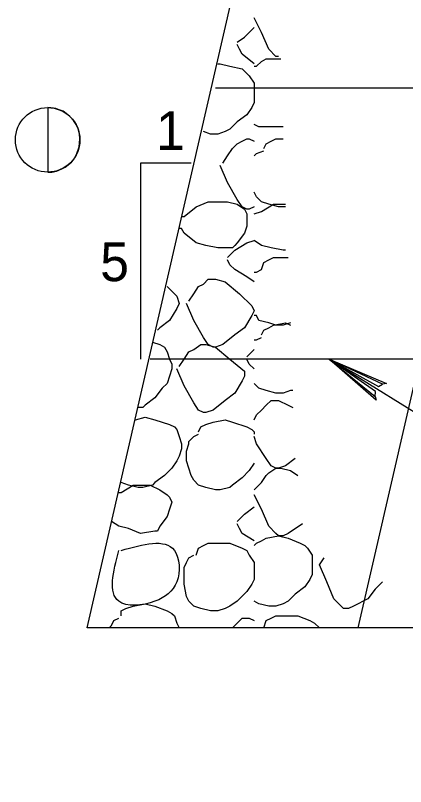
# Model space of a CAD drawing. Extents: x 593 to 1473, y 721 to 1315.
# Drawn here: x 987.5 to 1017.8, y 818.6 to 878.4 of the extents above; entities that cross this region are included whole.
import ezdxf

# ---------------------------------------------------------------- set-up
doc = ezdxf.new("R2010")
doc.units = 0
doc.layers.add('1', color=7, linetype='Continuous')
doc.layers.add('2', color=7, linetype='Continuous')

msp = doc.modelspace()

# ---------------------------------------------------------------- linework, layer by layer
at = {"layer": '1'}
msp.add_lwpolyline([(990.028, 871.224), (990.028, 866.22), (990.347, 866.231), (990.72, 866.305), (991.125, 866.465), (991.381, 866.604), (991.626, 866.785), (991.861, 866.999), (992.042, 867.212), (992.298, 867.66), (992.479, 868.194), (992.532, 868.781), (992.49, 869.197), (992.394, 869.581), (992.234, 869.922), (992.031, 870.232), (991.744, 870.541), (991.467, 870.765), (991.221, 870.936), (990.923, 871.043), (990.656, 871.15), (990.486, 871.182), (990.283, 871.214)], close=True, dxfattribs=at)
msp.add_lwpolyline([(1015.402, 848.857), (1015.432, 849.226), (1011.844, 851.735), (1015.402, 848.857), (1015.495, 848.565), (1011.844, 851.735), (1015.67, 849.616), (1015.977, 849.808), (1011.844, 851.735), (1016.3, 849.864), (1015.977, 849.808)], dxfattribs=at)
msp.add_lwpolyline([(1015.402, 848.857), (1015.432, 849.226), (1011.844, 851.735), (1015.402, 848.857), (1015.495, 848.565), (1011.844, 851.735), (1015.67, 849.616), (1015.977, 849.808), (1011.844, 851.735), (1016.3, 849.864), (1015.977, 849.808)], dxfattribs=at)
msp.add_circle((990.028, 868.722), 2.502, dxfattribs=at)
at = {"layer": '2'}
for p, q in [((993.094, 830.922), (1006.031, 887.172)), ((1014.094, 830.922), (1027.031, 887.172)), ((1037.531, 872.735), (1003.031, 872.735)), ((990.028, 871.224), (990.028, 866.22)), ((1001.156, 866.922), (997.219, 866.922)), ((997.219, 866.922), (997.219, 851.735)), ((1047.844, 851.735), (997.969, 851.735)), ((1011.844, 851.735), (1065.226, 818.633)), ((1027.969, 830.922), (993.094, 830.922))]:
    msp.add_line(p, q, dxfattribs=at)
for points in [[(1006.594, 877.047), (1006.031, 878.172)], [(1005.281, 876.672), (1006.031, 877.422)], [(1007.156, 875.735), (1006.594, 877.047)], [(1004.719, 876.297), (1005.281, 876.672)], [(1004.906, 875.735), (1004.719, 876.11)], [(1005.094, 875.36), (1004.906, 875.735)], [(1007.719, 875.172), (1007.156, 875.735)], [(1006.031, 874.61), (1005.094, 875.36)], [(1007.906, 875.172), (1007.719, 875.172)], [(1007.906, 875.172), (1007.906, 875.172)], [(1003.219, 874.61), (1003.406, 874.61)], [(1003.406, 874.61), (1004.156, 874.422)], [(1004.156, 874.422), (1005.094, 874.235)], [(1006.031, 874.422), (1006.219, 874.422)], [(1006.219, 874.422), (1006.594, 874.797)], [(1006.594, 874.797), (1006.969, 874.985)], [(1006.969, 874.985), (1007.906, 874.985)], [(1007.906, 874.985), (1008.094, 874.985)], [(1005.094, 874.235), (1005.469, 873.86)], [(1005.469, 873.86), (1005.656, 873.672)], [(1005.656, 873.672), (1006.031, 873.11)], [(1006.031, 873.11), (1006.031, 872.547)], [(1006.031, 872.547), (1006.031, 872.172)], [(1006.031, 872.172), (1006.031, 871.61)], [(1006.031, 871.61), (1005.844, 871.235)], [(1005.844, 871.235), (1005.469, 870.672)], [(1005.469, 870.672), (1004.719, 870.11)], [(1004.719, 870.11), (1004.156, 869.547)], [(1006.406, 869.735), (1006.031, 869.922)], [(1007.156, 869.735), (1006.406, 869.735)], [(1007.719, 869.735), (1007.156, 869.735)], [(1008.281, 869.735), (1007.719, 869.735)], [(1002.656, 869.172), (1002.094, 869.36)], [(1003.219, 869.172), (1002.656, 869.172)], [(1003.781, 869.36), (1003.219, 869.172)], [(1004.156, 869.547), (1003.781, 869.36)], [(1004.719, 868.422), (1005.094, 868.61)], [(1005.094, 868.61), (1005.469, 868.797)], [(1005.469, 868.797), (1005.656, 868.797)], [(1005.656, 868.797), (1006.031, 868.61)], [(1006.969, 868.422), (1007.344, 868.61)], [(1007.344, 868.61), (1007.719, 868.797)], [(1007.719, 868.797), (1008.281, 868.797)], [(1003.969, 867.485), (1004.344, 868.047)], [(1004.344, 868.047), (1004.719, 868.422)], [(1006.219, 867.672), (1006.781, 867.86)], [(1006.781, 868.047), (1006.969, 868.422)], [(1003.594, 866.922), (1003.969, 867.485)], [(1006.031, 867.485), (1006.219, 867.672)], [(1003.969, 865.422), (1003.406, 866.735)], [(1004.719, 864.11), (1003.969, 865.422)], [(1006.219, 864.297), (1006.031, 864.672)], [(1006.594, 863.922), (1006.219, 864.297)], [(1001.531, 863.547), (1002.469, 863.922)], [(1002.469, 863.922), (1002.844, 863.922)], [(1002.844, 863.922), (1003.406, 863.922)], [(1003.406, 863.922), (1003.969, 863.922)], [(1003.969, 863.922), (1004.719, 863.735)], [(1005.094, 863.547), (1004.719, 864.11)], [(1004.719, 863.735), (1005.281, 863.36)], [(1007.156, 863.735), (1006.594, 863.922)], [(1006.594, 863.172), (1007.531, 863.735)], [(1007.906, 863.547), (1007.156, 863.735)], [(1007.531, 863.735), (1007.906, 863.735)], [(1007.906, 863.735), (1008.469, 863.735)], [(1000.594, 862.797), (1001.531, 863.547)], [(1005.469, 863.36), (1005.094, 863.547)], [(1005.281, 863.36), (1005.469, 862.985)], [(1005.656, 863.36), (1005.469, 863.36)], [(1006.031, 863.547), (1005.656, 863.36)], [(1006.031, 862.985), (1006.594, 863.172)], [(1008.469, 863.547), (1007.906, 863.547)], [(1000.406, 862.797), (1000.594, 862.797)], [(1005.469, 862.985), (1005.469, 862.797)], [(1005.469, 862.797), (1005.469, 862.047)], [(1000.406, 861.86), (1000.219, 861.86)], [(1000.594, 861.485), (1000.406, 861.86)], [(1005.469, 862.047), (1005.281, 861.485)], [(1001.531, 860.735), (1000.594, 861.485)], [(1005.281, 861.485), (1004.719, 860.735)], [(1002.281, 860.547), (1001.531, 860.735)], [(1004.531, 860.172), (1005.469, 860.735)], [(1004.719, 860.735), (1004.531, 860.547)], [(1005.469, 860.735), (1006.031, 860.922)], [(1006.594, 860.547), (1006.031, 860.922)], [(1003.219, 860.36), (1002.281, 860.547)], [(1004.344, 860.36), (1003.219, 860.36)], [(1003.969, 859.61), (1004.531, 860.172)], [(1004.531, 860.547), (1004.344, 860.36)], [(1007.344, 860.36), (1006.594, 860.547)], [(1008.281, 860.172), (1007.344, 860.36)], [(1008.469, 860.172), (1008.281, 860.172)], [(1007.156, 859.422), (1007.531, 859.61)], [(1007.531, 859.61), (1008.469, 859.61)], [(1008.469, 859.61), (1008.656, 859.61)], [(1004.156, 859.047), (1003.969, 859.422)], [(1004.531, 858.672), (1004.156, 859.047)], [(1006.594, 858.672), (1006.781, 859.235)], [(1006.781, 859.235), (1007.156, 859.422)], [(1005.469, 858.11), (1004.531, 858.672)], [(1006.031, 858.485), (1006.219, 858.485)], [(1006.219, 858.485), (1006.594, 858.672)], [(1002.094, 857.547), (1002.469, 857.922)], [(1002.469, 857.922), (1002.844, 857.922)], [(1002.844, 857.922), (1003.031, 857.922)], [(1003.031, 857.922), (1003.781, 857.735)], [(1003.781, 857.735), (1004.906, 856.797)], [(1006.031, 857.735), (1005.469, 858.11)], [(999.281, 857.36), (1000.031, 856.61)], [(1001.344, 856.797), (1001.719, 857.36)], [(1001.719, 857.36), (1002.094, 857.547)], [(1000.031, 856.61), (1000.219, 856.047)], [(1000.969, 856.235), (1001.344, 856.797)], [(1004.906, 856.797), (1005.844, 855.86)], [(1000.219, 856.047), (1000.031, 855.672)], [(1001.344, 854.735), (1000.781, 856.047)], [(1000.031, 855.672), (999.469, 854.735)], [(1005.844, 855.86), (1006.031, 855.485)], [(1006.031, 855.485), (1005.844, 855.11)], [(999.469, 854.735), (998.719, 854.172)], [(1002.094, 853.422), (1001.344, 854.735)], [(1005.844, 855.11), (1005.281, 854.172)], [(1006.219, 855.11), (1006.031, 855.11)], [(1006.406, 854.735), (1006.219, 855.11)], [(1007.156, 854.547), (1006.406, 854.735)], [(998.719, 854.172), (998.531, 853.985)], [(1005.281, 854.172), (1004.531, 853.61)], [(1006.781, 853.985), (1007.156, 854.172)], [(1007.719, 854.36), (1007.156, 854.547)], [(1007.156, 854.172), (1007.531, 854.36)], [(1007.531, 854.36), (1008.469, 854.547)], [(1008.281, 854.36), (1007.719, 854.36)], [(1008.844, 854.547), (1008.281, 854.36)], [(1008.469, 854.547), (1008.844, 854.36)], [(1004.531, 853.61), (1003.594, 852.86)], [(1006.594, 853.61), (1006.781, 853.985)], [(998.156, 853.047), (998.719, 852.86)], [(1002.469, 852.86), (1002.094, 853.422)], [(1006.031, 853.235), (1006.219, 853.235)], [(1006.219, 853.235), (1006.594, 853.422)], [(998.719, 852.86), (999.094, 852.672)], [(999.094, 852.672), (999.281, 852.297)], [(1000.969, 852.297), (1001.344, 852.485)], [(1001.344, 852.485), (1001.906, 852.86)], [(1001.906, 852.86), (1002.094, 852.86)], [(1002.094, 852.86), (1002.281, 852.86)], [(1002.281, 852.86), (1003.031, 852.672)], [(1002.844, 852.672), (1002.469, 852.86)], [(1003.031, 852.672), (1002.844, 852.672)], [(1003.594, 852.86), (1003.031, 852.672)], [(1003.031, 852.672), (1004.156, 851.735)], [(1005.469, 851.922), (1006.031, 852.485)], [(1006.031, 852.485), (1006.031, 852.485)], [(999.281, 852.297), (999.469, 851.735)], [(999.469, 851.735), (999.656, 851.36)], [(1000.219, 851.172), (1000.594, 851.735)], [(1000.594, 851.735), (1000.969, 852.297)], [(1004.156, 851.735), (1005.281, 850.797)], [(1005.656, 851.36), (1005.469, 851.735)], [(999.656, 851.36), (999.656, 850.985)], [(1006.031, 850.985), (1005.656, 851.36)], [(999.656, 850.985), (999.469, 850.422)], [(1000.594, 849.672), (1000.031, 850.985)], [(1005.281, 850.797), (1005.281, 850.422)], [(1006.031, 850.985), (1006.031, 850.985)], [(999.469, 850.422), (999.281, 849.86)], [(1005.094, 850.047), (1004.531, 849.11)], [(1005.281, 850.422), (1005.094, 850.047)], [(998.906, 849.485), (998.344, 848.735)], [(999.281, 849.86), (998.906, 849.485)], [(1001.344, 848.36), (1000.594, 849.672)], [(1006.406, 849.485), (1006.031, 849.86)], [(1006.031, 849.86), (1006.031, 849.86)], [(1006.969, 849.297), (1006.406, 849.485)], [(998.344, 848.735), (997.594, 848.172)], [(1004.531, 849.11), (1003.781, 848.547)], [(1007.719, 849.11), (1006.969, 849.297)], [(1008.281, 849.11), (1007.719, 849.11)], [(1008.844, 849.297), (1008.281, 849.11)], [(1009.031, 849.297), (1008.844, 849.297)], [(997.594, 848.172), (997.406, 847.985)], [(1001.719, 847.797), (1001.344, 848.36)], [(1003.781, 848.547), (1002.844, 847.797)], [(1006.594, 847.797), (1006.969, 848.172)], [(1006.969, 848.172), (1007.344, 848.547)], [(1007.344, 848.547), (1007.719, 848.547)], [(1007.719, 848.547), (1007.906, 848.547)], [(1007.906, 848.547), (1008.656, 848.172)], [(1008.656, 848.172), (1009.031, 847.985)], [(997.406, 847.985), (997.031, 847.985)], [(1002.094, 847.61), (1001.719, 847.797)], [(1002.281, 847.61), (1002.094, 847.61)], [(1002.844, 847.797), (1002.281, 847.61)], [(1006.219, 847.422), (1006.594, 847.797)], [(996.844, 847.047), (997.594, 847.235)], [(997.594, 847.235), (998.344, 847.047)], [(998.344, 847.047), (999.469, 846.672)], [(1002.844, 846.86), (1003.781, 847.047)], [(1003.781, 847.047), (1004.344, 846.86)], [(1006.031, 847.047), (1006.219, 847.422)], [(999.469, 846.672), (999.844, 846.485)], [(999.844, 846.485), (1000.031, 846.297)], [(1001.719, 846.11), (1001.906, 846.485)], [(1001.906, 846.485), (1002.281, 846.672)], [(1002.281, 846.672), (1002.844, 846.86)], [(1004.344, 846.86), (1005.469, 846.485)], [(1005.469, 846.485), (1005.844, 846.297)], [(1000.031, 846.297), (1000.219, 845.735)], [(1000.219, 845.735), (1000.406, 845.172)], [(1000.969, 845.36), (1001.344, 845.735)], [(1001.344, 845.735), (1001.719, 845.922)], [(1005.844, 846.297), (1006.031, 846.11)], [(1006.031, 846.11), (1006.031, 845.922)], [(1006.219, 845.172), (1006.031, 845.735)], [(1000.406, 845.172), (1000.406, 844.797)], [(1000.781, 844.61), (1000.969, 845.172)], [(1000.969, 845.172), (1000.969, 845.36)], [(1006.969, 844.047), (1006.219, 845.172)], [(1000.406, 844.797), (1000.219, 844.235)], [(1000.781, 843.86), (1000.781, 844.61)], [(1000.219, 844.235), (1000.031, 843.86)], [(1007.344, 843.485), (1006.969, 844.047)], [(1009.219, 844.047), (1008.469, 843.485)], [(1000.031, 843.86), (999.656, 843.297)], [(1001.156, 842.735), (1000.781, 843.86)], [(1006.031, 843.672), (1005.656, 843.11)], [(1006.031, 843.672), (1006.031, 843.672)], [(1007.719, 843.297), (1007.344, 843.485)], [(1008.469, 843.485), (1007.906, 843.297)], [(999.656, 843.297), (999.094, 842.735)], [(1005.656, 843.11), (1005.094, 842.547)], [(1006.969, 842.735), (1007.156, 842.922)], [(1007.156, 842.922), (1007.719, 843.297)], [(1007.719, 843.297), (1007.906, 843.297)], [(1007.906, 843.297), (1007.719, 843.297)], [(1007.906, 843.297), (1008.094, 843.297)], [(1008.094, 843.297), (1008.844, 843.11)], [(1008.844, 843.11), (1009.406, 842.735)], [(996.281, 841.985), (995.719, 842.172)], [(998.344, 842.172), (998.156, 841.985)], [(999.094, 842.735), (998.344, 842.172)], [(1001.344, 842.36), (1001.156, 842.735)], [(1001.719, 841.985), (1001.344, 842.36)], [(1005.094, 842.547), (1004.344, 841.985)], [(1006.031, 841.61), (1006.594, 842.172)], [(1006.594, 842.172), (1006.969, 842.735)], [(995.719, 841.422), (996.656, 841.985)], [(997.031, 841.797), (996.281, 841.985)], [(996.656, 841.985), (996.844, 841.985)], [(996.844, 841.985), (997.594, 841.985)], [(997.406, 841.797), (997.031, 841.797)], [(998.156, 841.985), (997.406, 841.797)], [(997.594, 841.985), (997.969, 841.985)], [(997.969, 841.985), (998.719, 841.61)], [(998.719, 841.61), (999.281, 841.235)], [(1002.281, 841.797), (1001.719, 841.985)], [(1003.031, 841.61), (1002.281, 841.797)], [(1003.406, 841.61), (1003.031, 841.61)], [(1004.156, 841.797), (1003.406, 841.61)], [(1004.344, 841.985), (1004.156, 841.797)], [(995.531, 841.422), (995.719, 841.422)], [(999.281, 841.235), (999.469, 841.047)], [(999.469, 841.047), (999.656, 840.672)], [(1006.594, 840.11), (1006.031, 841.235)], [(999.656, 840.672), (999.469, 840.11)], [(999.469, 840.11), (999.281, 839.547)], [(1005.281, 839.735), (1006.031, 840.297)], [(1007.156, 838.797), (1006.594, 840.11)], [(995.531, 838.797), (994.969, 839.172)], [(999.281, 839.547), (998.719, 838.797)], [(1004.719, 839.172), (1005.281, 839.735)], [(996.281, 838.61), (995.531, 838.797)], [(997.219, 838.235), (996.281, 838.61)], [(998.719, 838.797), (998.531, 838.422)], [(1004.906, 838.61), (1004.719, 838.985)], [(1005.094, 838.235), (1004.906, 838.61)], [(1007.719, 838.235), (1007.156, 838.797)], [(1009.781, 838.985), (1008.656, 838.235)], [(1009.781, 838.985), (1009.781, 838.985)], [(998.344, 838.422), (997.219, 838.235)], [(998.531, 838.422), (998.344, 838.422)], [(1006.031, 837.672), (1005.094, 838.235)], [(1006.969, 837.86), (1007.906, 838.047)], [(1007.906, 838.047), (1007.719, 838.235)], [(1007.906, 838.047), (1008.656, 837.86)], [(1008.281, 838.047), (1007.906, 838.047)], [(1008.656, 838.235), (1008.281, 838.047)], [(1002.094, 837.297), (1002.469, 837.485)], [(1002.469, 837.485), (1003.406, 837.485)], [(1003.406, 837.485), (1004.156, 837.485)], [(1004.156, 837.485), (1005.094, 837.11)], [(1006.031, 837.297), (1006.219, 837.485)], [(1006.219, 837.485), (1006.594, 837.672)], [(1006.594, 837.672), (1006.969, 837.86)], [(1008.656, 837.86), (1009.594, 837.485)], [(1009.594, 837.485), (1009.969, 837.297)], [(1001.531, 836.547), (1001.719, 837.11)], [(1001.719, 837.11), (1002.094, 837.297)], [(1005.094, 837.11), (1005.469, 836.922)], [(1005.469, 836.922), (1005.656, 836.547)], [(1009.969, 837.297), (1010.156, 837.11)], [(1010.156, 837.11), (1010.531, 836.547)], [(1000.781, 835.985), (1000.969, 836.36)], [(1000.969, 836.36), (1001.344, 836.547)], [(1005.656, 836.547), (1006.031, 835.985)], [(1010.531, 836.547), (1010.531, 835.985)], [(1011.094, 835.797), (1011.469, 836.36)], [(1000.594, 835.61), (1000.781, 835.985)], [(1000.594, 835.047), (1000.594, 835.61)], [(1006.031, 835.985), (1006.031, 835.61)], [(1006.031, 835.61), (1006.031, 835.235)], [(1010.531, 835.985), (1010.531, 835.61)], [(1010.531, 835.61), (1010.531, 835.047)], [(1011.656, 834.485), (1011.094, 835.797)], [(1000.594, 834.297), (1000.594, 835.047)], [(1006.031, 835.235), (1006.031, 834.672)], [(1010.531, 835.047), (1010.344, 834.672)], [(1006.031, 834.672), (1005.844, 834.297)], [(1010.344, 834.672), (1009.969, 834.11)], [(1012.219, 833.172), (1011.656, 834.485)], [(1015.969, 834.485), (1015.406, 833.922)], [(1000.781, 833.36), (1000.594, 834.297)], [(1005.844, 834.297), (1005.469, 833.735)], [(1009.969, 834.11), (1009.219, 833.547)], [(1015.406, 833.922), (1014.844, 833.172)], [(1000.969, 832.985), (1000.781, 833.36)], [(1005.469, 833.735), (1004.719, 832.985)], [(1009.219, 833.547), (1008.656, 832.985)], [(996.094, 832.422), (996.656, 832.61)], [(996.656, 832.61), (997.594, 832.797)], [(997.594, 832.797), (998.344, 832.61)], [(998.344, 832.61), (999.281, 832.235)], [(1001.344, 832.61), (1000.969, 832.985)], [(1001.906, 832.422), (1001.344, 832.61)], [(1004.156, 832.61), (1003.781, 832.422)], [(1004.719, 832.985), (1004.156, 832.61)], [(1006.406, 832.797), (1006.031, 832.985)], [(1007.156, 832.61), (1006.406, 832.797)], [(1007.719, 832.61), (1007.156, 832.61)], [(1008.281, 832.797), (1007.719, 832.61)], [(1008.656, 832.985), (1008.281, 832.797)], [(1012.781, 832.61), (1012.219, 833.172)], [(1012.969, 832.422), (1012.781, 832.61)], [(1013.719, 832.61), (1013.344, 832.422)], [(1014.844, 833.172), (1013.719, 832.61)], [(995.719, 832.235), (996.094, 832.422)], [(995.719, 831.86), (995.719, 832.235)], [(999.281, 832.235), (999.656, 832.047)], [(999.656, 832.047), (999.844, 831.86)], [(1002.656, 832.235), (1001.906, 832.422)], [(1003.219, 832.235), (1002.656, 832.235)], [(1003.781, 832.422), (1003.219, 832.235)], [(1013.344, 832.422), (1012.969, 832.422)], [(994.969, 831.11), (995.156, 831.485)], [(995.156, 831.485), (995.531, 831.672)], [(999.844, 831.86), (1000.031, 831.297)], [(1004.719, 831.297), (1005.094, 831.672)], [(1005.094, 831.672), (1005.469, 831.672)], [(1005.469, 831.672), (1005.656, 831.672)], [(1005.656, 831.672), (1006.031, 831.485)], [(1006.781, 830.922), (1006.969, 831.485)], [(1006.969, 831.485), (1007.344, 831.672)], [(1007.344, 831.672), (1007.719, 831.86)], [(1007.719, 831.86), (1008.656, 831.86)], [(1008.656, 831.86), (1009.406, 831.86)], [(1009.406, 831.86), (1010.344, 831.485)], [(1010.344, 831.485), (1010.719, 831.297)], [(994.781, 830.922), (994.969, 831.11)], [(1000.031, 831.297), (1000.219, 830.922)], [(1004.344, 830.922), (1004.719, 831.297)], [(1004.344, 830.922), (1004.344, 830.922)], [(1010.719, 831.297), (1011.094, 830.922)]]:
    msp.add_lwpolyline(points, dxfattribs=at)
msp.add_spline([(995.719, 836.922), (999.844, 836.922), (1000.031, 834.485), (998.344, 832.985), (995.531, 832.985), (995.531, 836.922)], degree=3, dxfattribs=at)

# ---------------------------------------------------------------- texts
for s, p in [('1', (998.419, 867.941)), ('5', (994.101, 857.778))]:
    msp.add_text(s, height=3, dxfattribs=at).set_placement(p)

doc.saveas('drawing.dxf')
